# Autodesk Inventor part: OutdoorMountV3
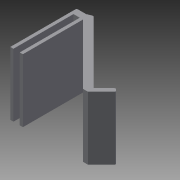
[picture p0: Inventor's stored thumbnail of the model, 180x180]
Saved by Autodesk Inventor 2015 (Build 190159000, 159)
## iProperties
Created: 2017-04
Part Number: OutdoorMountV3
Material: Generisch
Document SubType Name: Modeling
Designer: Andreas
Density: 1 g/cm^3
Appearance: Vorgabe
Author: Andreas
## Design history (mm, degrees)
sketch "Skizze1"
  geometry: L1 (0, 0)-(0, 105); L2 (0, 105)-(20, 105); L3 (0, 0)-(5, 0); L4 (5, 0)-(5, 95); L5 (5, 95)-(15, 95); L6 (15, 95)-(15, 0); L7 (15, 0)-(20, 0); L8 (20, 0)-(20, 95); L9 (25, 105)-(143.136, 105); L10 (20, 95)-(115, 0); L11 (20, 95)-(154.35, 95); L12 (118.995, 6.005)-(20, 105); L13 (118.995, 6.005)-(258.995, 6.005); L14 (118.995, 6.005)-(140.208, 27.218); L15 (118.995, 6.005)-(148.995, 6.005); L16 (140.208, 27.218)-(145.158, 22.269); L17 (145.158, 22.269)-(122.889, 0); L18 (122.889, 0)-(115, 0)
  constraints: 36 end point, 8 horizontal, 5 perpendicular, 3 equal length, 2 vertical, 1 point on line
  dimensions: "d0" = 105 distance of L1.start L1.end; "d2" = 5 distance of L1.start L3.end; "d3" = 95 distance of L3.end L4.end; "d4" = 10 distance of L4.end L5.end; "d5" = 5 distance of L6.end L7.end; "d6" = 95 distance of L7.end L8.end; "d27" = 45 deg angle of L10 L11; "d29" = 135 deg angle of L13 L12; "d30" = 30 distance of L12.start L14.end; "d31" = 45 deg angle of L15 L14 (derived); "d34" = 140 distance of L12.start L2.end; "d35" = 20 distance of L1.end L2.end; "d36" = 7 distance of L14.end L16.end; "d37" = 7.88939 distance of L17.end L10.end; "d38" = 135 deg angle of L18 L17
extrude "Extrusion1" new body sketch "Skizze1" distance "d39" = 100; taper "d40" = 0 deg
sketch "Skizze2"
  geometry: L1 (-20, 70)-(-120, 70); L2 (-120, 70)-(-120, 30); L3 (-120, 30)-(-20, 30); L4 (-20, 30)-(-20, 70); 3 further points
  constraints: 8 end point, 2 parallel, 1 horizontal, 1 perpendicular
  dimensions: "d63" = 100 distance of L3.end L2.end; "d64" = 40 distance of L2.end L1.end
extrude "Extrusion2" cut sketch "Skizze2" distance "d42" = 8; taper "d43" = 0 deg
sketch "Skizze3"
  geometry: L1 (20, 105)-(25, 105); L2 (23.536, 108.536)-(122.53, 9.541); L3 (140.208, 27.218)-(118.995, 6.005) reference; L4 (122.53, 9.541)-(118.995, 6.005); L5 (118.995, 6.005)-(20, 105); L6 (20, 105)-(0, 105) reference; L7 (23.536, 108.536)-(15, 105); 1 further point
  constraints: 10 end point, 2 point on line, 1 collinear, 1 horizontal
  dimensions: "d44" = 5 distance of L1.start L2.start; "d47" = 112.5 deg angle of L2 L7; "d48" = 157.5 deg angle of L7 L6; "d49" = 8.53553 horizontal distance of L2.start L7.end
extrude "Extrusion3" join sketch "Skizze3" distance "d50" = 2.5; taper "d51" = 0 deg
sketch "Skizze4"
  geometry: L1 (-20, 105)-(-118.995, 6.005); L2 (-118.995, 6.005)-(-122.53, 9.541); L3 (-122.53, 9.541)-(-23.536, 108.536); L4 (-23.536, 108.536)-(-122.53, 9.541) reference; L5 (-23.536, 108.536)-(-15, 105); L6 (-15, 105)-(-23.536, 108.536) reference; L7 (-15, 105)-(-20, 105); L8 (0, 105)-(-20, 105) reference; L9 (-118.995, 6.005)-(-140.208, 27.218) reference; 1 further point
  constraints: 10 end point, 3 collinear
  dimensions: "d52" = 5 distance of L1.end L2.end
extrude "Extrusion4" join sketch "Skizze4" distance "d53" = 2.5; taper "d54" = 0 deg
fillet "Rundung1" dims "d55" = 3
fillet "Rundung2" dims "d56" = 3
fillet "Rundung3" dims "d57" = 2
fillet "Rundung4" dims "d58" = 2
fillet "Rundung7" dims "d61" = 2
fillet "Rundung8" dims "d62" = 2
fillet "Rundung9" dims "d65" = 2
node "Volumenkörper1"
